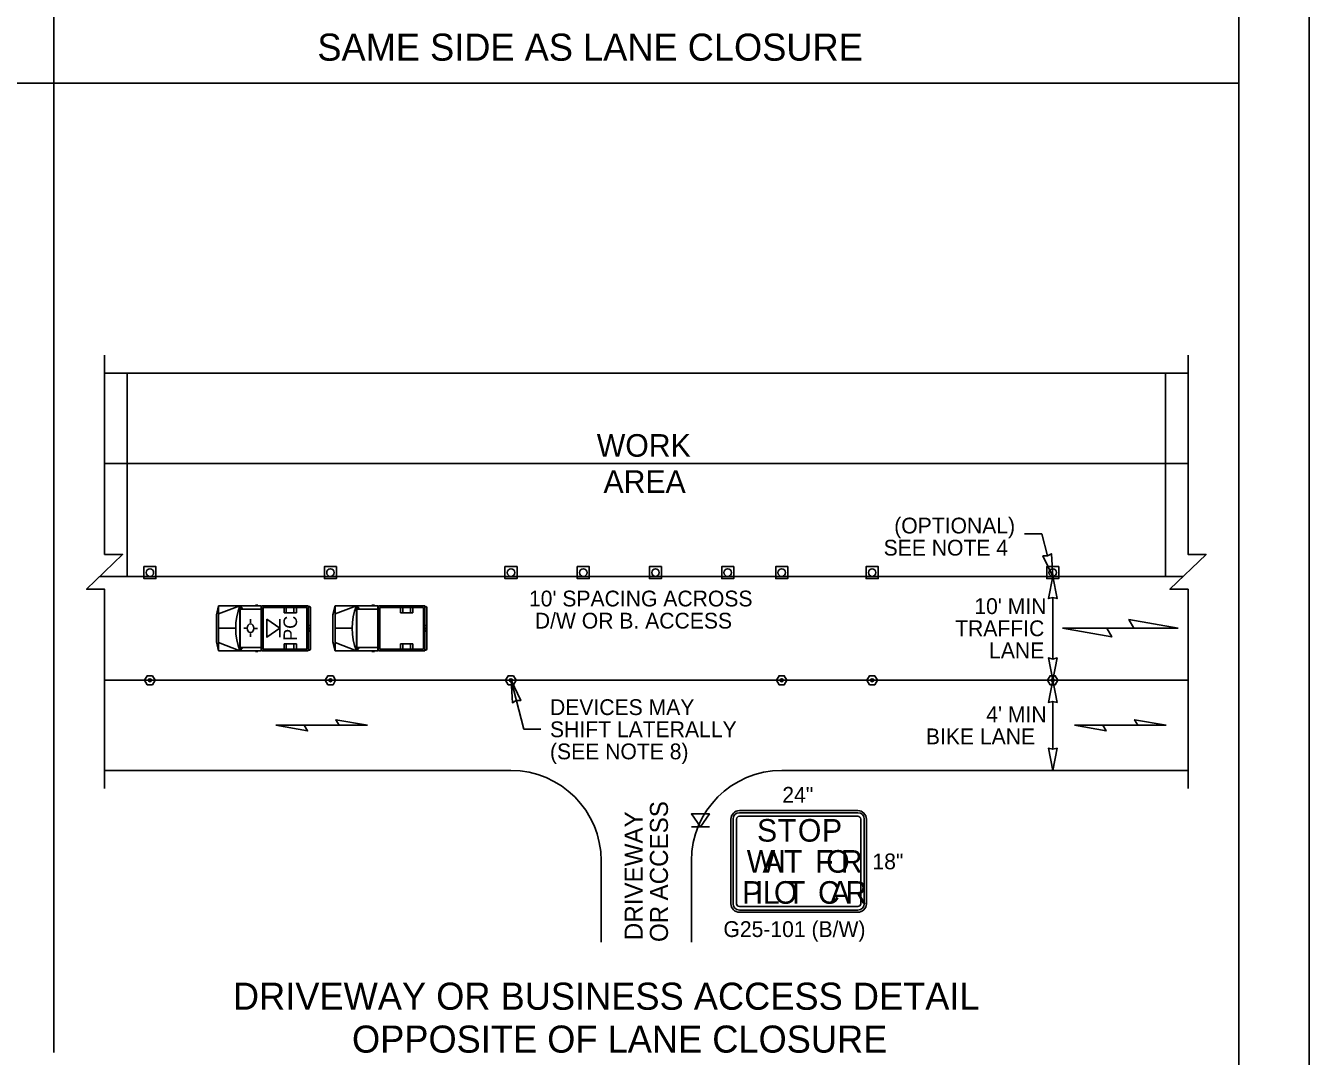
# Model space of a CAD drawing. Extents: x 99999.1 to 100095.7, y 99995 to 100010.7.
# Drawn here: x 100070.38 to 100076.06, y 100001.67 to 100006.24 of the extents above; entities that cross this region are included whole.
import ezdxf

# ---------------------------------------------------------------- set-up
doc = ezdxf.new("R2010")
doc.units = 0
for name, color, linetype in [('RD_ED_DrivewayEdge', 7, 'Continuous'), ('RD_ED_ShoulderPavedEdge', 7, 'Continuous'), ('RD_MK_LineEdgeWhite', 7, 'Continuous'), ('RD_MK_LineSkipCenter', 7, 'Continuous'), ('SH_DE_DetailHeading2Text', 7, 'Continuous'), ('SH_GI_PlotLimits', 7, 'Continuous'), ('SH_GI_SheetBorder', 7, 'Continuous'), ('TR_SN_ConstructionSigns', 7, 'Continuous'), ('TR_WZ_MotoristVehicle', 7, 'Continuous'), ('TR_WZ_PortableSignMountBlk-Wht', 7, 'Continuous'), ('TR_WZ_TrafficCone', 7, 'Continuous'), ('TR_WZ_TubularMarker', 7, 'Continuous'), ('TR_WZ_WorkAreaLabel', 7, 'Continuous'), ('TR_WZ_WorkZoneDetails', 7, 'Continuous'), ('TR_WZ_WorkZoneTextCurrent', 7, 'Continuous')]:
    doc.layers.add(name, color=color, linetype=linetype)

msp = doc.modelspace()

# ---------------------------------------------------------------- linework, layer by layer
at = {"layer": 'RD_ED_DrivewayEdge'}
for p, q in [((100072.925, 100002.5359), (100072.925, 100002.1759)), ((100073.325, 100002.5359), (100073.325, 100002.1759))]:
    msp.add_line(p, q, dxfattribs=at)
for centre, start, end in [((100072.525, 100002.5359), 0, 90), ((100073.725, 100002.5359), 90, 180)]:
    msp.add_arc(centre, 0.4, start, end, dxfattribs=at)
at = {"layer": 'RD_ED_ShoulderPavedEdge'}
for p, q in [((100070.725, 100004.6959), (100075.525, 100004.6959)), ((100070.725, 100002.9359), (100072.525, 100002.9359)), ((100073.725, 100002.9359), (100075.525, 100002.9359))]:
    msp.add_line(p, q, dxfattribs=at)
at = {"layer": 'RD_MK_LineEdgeWhite'}
for p, q in [((100070.725, 100004.2959), (100075.525, 100004.2959)), ((100070.725, 100003.3359), (100075.525, 100003.3359))]:
    msp.add_line(p, q, dxfattribs=at)
at = {"layer": 'RD_MK_LineSkipCenter'}
msp.add_lwpolyline([(100075.5043, 100003.7959), (100070.7043, 100003.7959)], dxfattribs=at)
at = {"layer": 'SH_GI_PlotLimits'}
msp.add_lwpolyline([(100059.0625, 99999.6875), (100076.0625, 99999.6875), (100076.0625, 100010.6875), (100059.0625, 100010.6875)], close=True, dxfattribs=at)
at = {"layer": 'SH_GI_SheetBorder'}
msp.add_line((100075.75, 100010.375), (100075.75, 100000), dxfattribs=at)
at = {"layer": 'TR_SN_ConstructionSigns'}
for p, q in [((100073.5, 100002.3456), (100073.5, 100002.7206)), ((100073.5, 100002.7206), (100073.5, 100002.3456)), ((100073.5094, 100002.7206), (100073.5094, 100002.3456)), ((100073.525, 100002.3456), (100073.525, 100002.7206)), ((100073.5375, 100002.7581), (100074.0625, 100002.7581)), ((100074.0625, 100002.7581), (100073.5375, 100002.7581)), ((100074.0625, 100002.7488), (100073.5375, 100002.7488)), ((100073.5375, 100002.7331), (100074.0625, 100002.7331)), ((100074.075, 100002.7206), (100074.075, 100002.3456)), ((100074.0906, 100002.3456), (100074.0906, 100002.7206)), ((100074.1, 100002.7206), (100074.1, 100002.3456)), ((100074.1, 100002.3456), (100074.1, 100002.7206)), ((100074.0625, 100002.3331), (100073.5375, 100002.3331)), ((100073.5375, 100002.3175), (100074.0625, 100002.3175)), ((100074.0625, 100002.3081), (100073.5375, 100002.3081)), ((100073.5375, 100002.3081), (100074.0625, 100002.3081))]:
    msp.add_line(p, q, dxfattribs=at)
for centre, radius, start, end in [((100073.5375, 100002.7206), 0.0375, 90, 180), ((100073.5375, 100002.7206), 0.0375, 90, 180), ((100073.5375, 100002.7206), 0.0281, 90, 180), ((100073.5375, 100002.7206), 0.0125, 90, 180), ((100074.0625, 100002.7206), 0.0375, 0, 90), ((100074.0625, 100002.7206), 0.0375, 0, 90), ((100074.0625, 100002.7206), 0.0281, 0, 90), ((100074.0625, 100002.7206), 0.0125, 0, 90), ((100073.5375, 100002.3456), 0.0375, 180, 270), ((100073.5375, 100002.3456), 0.0375, 180, 270), ((100073.5375, 100002.3456), 0.0281, 180, 270), ((100073.5375, 100002.3456), 0.0125, 180, 270), ((100074.0625, 100002.3456), 0.0375, 270, 0), ((100074.0625, 100002.3456), 0.0375, 270, 0), ((100074.0625, 100002.3456), 0.0281, 270, 0), ((100074.0625, 100002.3456), 0.0125, 270, 0)]:
    msp.add_arc(centre, radius, start, end, dxfattribs=at)
at = {"layer": 'TR_WZ_MotoristVehicle'}
for p, q in [((100071.23, 100003.6659), (100071.2207, 100003.6255)), ((100071.2207, 100003.6255), (100071.2207, 100003.5063)), ((100071.23, 100003.6659), (100071.23, 100003.4659)), ((100071.23, 100003.6659), (100071.4189, 100003.6659)), ((100071.23, 100003.6293), (100071.3245, 100003.6659)), ((100071.3245, 100003.6659), (100071.3245, 100003.4659)), ((100071.3262, 100003.6659), (100071.3262, 100003.4659)), ((100071.3262, 100003.6659), (100071.3382, 100003.6504)), ((100071.3262, 100003.6504), (100071.4189, 100003.6504)), ((100071.3932, 100003.6687), (100071.4045, 100003.6687)), ((100071.4189, 100003.6659), (100071.4189, 100003.4659)), ((100071.6274, 100003.6659), (100071.4217, 100003.6659)), ((100071.4217, 100003.6659), (100071.4217, 100003.4659)), ((100071.6215, 100003.6579), (100071.4275, 100003.6579)), ((100071.4275, 100003.6579), (100071.4275, 100003.4739)), ((100071.5202, 100003.6579), (100071.5202, 100003.6349)), ((100071.5752, 100003.6349), (100071.5202, 100003.6349)), ((100071.5302, 100003.6579), (100071.5302, 100003.6349)), ((100071.5642, 100003.6579), (100071.5642, 100003.6349)), ((100071.5752, 100003.6579), (100071.5752, 100003.6349)), ((100071.6215, 100003.6579), (100071.6215, 100003.4739)), ((100071.6274, 100003.6659), (100071.6274, 100003.4659)), ((100071.6325, 100003.6626), (100071.6281, 100003.6626)), ((100071.6281, 100003.6626), (100071.6281, 100003.4692)), ((100071.637, 100003.6565), (100071.637, 100003.4753)), ((100071.7463, 100003.6659), (100071.737, 100003.6255)), ((100071.737, 100003.6255), (100071.737, 100003.5063)), ((100071.7463, 100003.6659), (100071.7463, 100003.4659)), ((100071.7463, 100003.6659), (100071.9352, 100003.6659)), ((100071.7463, 100003.6293), (100071.8407, 100003.6659)), ((100071.8407, 100003.6659), (100071.8407, 100003.4659)), ((100071.8424, 100003.6659), (100071.8424, 100003.4659)), ((100071.8424, 100003.6659), (100071.8545, 100003.6504)), ((100071.8424, 100003.6504), (100071.9352, 100003.6504)), ((100071.9094, 100003.6687), (100071.9207, 100003.6687)), ((100071.9352, 100003.6659), (100071.9352, 100003.4659)), ((100072.1436, 100003.6659), (100071.9379, 100003.6659)), ((100071.9379, 100003.6659), (100071.9379, 100003.4659)), ((100072.1378, 100003.6579), (100071.9438, 100003.6579)), ((100071.9438, 100003.6579), (100071.9438, 100003.4739)), ((100072.0365, 100003.6579), (100072.0365, 100003.6349)), ((100072.0914, 100003.6349), (100072.0365, 100003.6349)), ((100072.0465, 100003.6579), (100072.0465, 100003.6349)), ((100072.0805, 100003.6579), (100072.0805, 100003.6349)), ((100072.0914, 100003.6579), (100072.0914, 100003.6349)), ((100072.1378, 100003.6579), (100072.1378, 100003.4739)), ((100072.1436, 100003.6659), (100072.1436, 100003.4659)), ((100072.1488, 100003.6626), (100072.1443, 100003.6626)), ((100072.1443, 100003.6626), (100072.1443, 100003.4692)), ((100072.1533, 100003.6565), (100072.1533, 100003.4753)), ((100071.3715, 100003.6055), (100071.3715, 100003.5894)), ((100071.637, 100003.58), (100071.6281, 100003.5762)), ((100071.6325, 100003.5687), (100071.6325, 100003.5631)), ((100072.1533, 100003.58), (100072.1443, 100003.5762)), ((100072.1488, 100003.5687), (100072.1488, 100003.5631)), ((100071.23, 100003.5659), (100071.3059, 100003.5659)), ((100071.3414, 100003.566), (100071.354, 100003.566)), ((100071.3722, 100003.5274), (100071.3719, 100003.5425)), ((100071.3856, 100003.5656), (100071.3856, 100003.5656)), ((100071.4024, 100003.5651), (100071.3875, 100003.5655)), ((100071.637, 100003.5518), (100071.6281, 100003.5556)), ((100071.6346, 100003.5659), (100071.6305, 100003.5659)), ((100071.7463, 100003.5659), (100071.8222, 100003.5659)), ((100072.1533, 100003.5518), (100072.1443, 100003.5556)), ((100072.1509, 100003.5659), (100072.1467, 100003.5659)), ((100071.23, 100003.4659), (100071.2207, 100003.5063)), ((100071.23, 100003.5025), (100071.3245, 100003.4659)), ((100071.23, 100003.4659), (100071.4189, 100003.4659)), ((100071.3262, 100003.4814), (100071.4189, 100003.4814)), ((100071.3361, 100003.4814), (100071.3262, 100003.4659)), ((100071.3932, 100003.4631), (100071.4045, 100003.4631)), ((100071.6274, 100003.4659), (100071.4217, 100003.4659)), ((100071.6215, 100003.4739), (100071.4275, 100003.4739)), ((100071.5202, 100003.4739), (100071.5202, 100003.4969)), ((100071.5752, 100003.4969), (100071.5202, 100003.4969)), ((100071.5302, 100003.4739), (100071.5302, 100003.4969)), ((100071.5642, 100003.4739), (100071.5642, 100003.4969)), ((100071.5752, 100003.4739), (100071.5752, 100003.4969)), ((100071.6325, 100003.4692), (100071.6281, 100003.4692)), ((100071.7463, 100003.4659), (100071.737, 100003.5063)), ((100071.7463, 100003.5025), (100071.8407, 100003.4659)), ((100071.7463, 100003.4659), (100071.9352, 100003.4659)), ((100071.8424, 100003.4814), (100071.9352, 100003.4814)), ((100071.8524, 100003.4814), (100071.8424, 100003.4659)), ((100071.9094, 100003.4631), (100071.9207, 100003.4631)), ((100072.1436, 100003.4659), (100071.9379, 100003.4659)), ((100072.1378, 100003.4739), (100071.9438, 100003.4739)), ((100072.0365, 100003.4739), (100072.0365, 100003.4969)), ((100072.0914, 100003.4969), (100072.0365, 100003.4969)), ((100072.0465, 100003.4739), (100072.0465, 100003.4969)), ((100072.0805, 100003.4739), (100072.0805, 100003.4969)), ((100072.0914, 100003.4739), (100072.0914, 100003.4969)), ((100072.1488, 100003.4692), (100072.1443, 100003.4692))]:
    msp.add_line(p, q, dxfattribs=at)
for centre, major_axis, start_param, end_param in [((100071.4595, 100003.5659), (0, -0.2099), 4.215667, 5.208926), ((100071.6325, 100003.6565), (0, 0.0061), 4.712389, 6.283185), ((100071.9757, 100003.5659), (0, -0.2099), 4.215667, 5.208926), ((100072.1488, 100003.6565), (0, 0.0061), 4.712389, 6.283185), ((100071.6325, 100003.4753), (0, -0.0061), 0, 1.570796), ((100072.1488, 100003.4753), (0, -0.0061), 0, 1.570796)]:
    msp.add_ellipse(centre, major_axis=major_axis, ratio=0.73155, start_param=start_param, end_param=end_param, dxfattribs=at)
for centre, major_axis in [((100071.3715, 100003.5659), (0, 0.0193)), ((100071.6325, 100003.5659), (0, 0.00282)), ((100072.1488, 100003.5659), (0, 0.00282))]:
    msp.add_ellipse(centre, major_axis=major_axis, ratio=0.73155, dxfattribs=at)
at = {"layer": 'TR_WZ_PortableSignMountBlk-Wht'}
for p, q in [((100071.5013, 100003.6058), (100071.5013, 100003.5258)), ((100073.405, 100002.6859), (100073.325, 100002.6859))]:
    msp.add_line(p, q, dxfattribs=at)
for points in [[(100071.5013, 100003.5659), (100071.4439, 100003.5258), (100071.4439, 100003.6058)], [(100073.3651, 100002.6859), (100073.325, 100002.7434), (100073.405, 100002.7434)]]:
    msp.add_lwpolyline(points, close=True, dxfattribs=at)
at = {"layer": 'TR_WZ_TrafficCone'}
for points in [[(100070.899, 100003.8392), (100070.9524, 100003.8392), (100070.9524, 100003.7859), (100070.899, 100003.7859), (100070.899, 100003.8392)], [(100070.899, 100003.7859), (100070.9524, 100003.7859), (100070.9524, 100003.8392), (100070.899, 100003.8392), (100070.899, 100003.7859)], [(100071.699, 100003.8392), (100071.7524, 100003.8392), (100071.7524, 100003.7859), (100071.699, 100003.7859), (100071.699, 100003.8392)], [(100071.699, 100003.7859), (100071.7524, 100003.7859), (100071.7524, 100003.8392), (100071.699, 100003.8392), (100071.699, 100003.7859)], [(100072.499, 100003.8392), (100072.5524, 100003.8392), (100072.5524, 100003.7859), (100072.499, 100003.7859), (100072.499, 100003.8392)], [(100072.499, 100003.7859), (100072.5524, 100003.7859), (100072.5524, 100003.8392), (100072.499, 100003.8392), (100072.499, 100003.7859)], [(100072.819, 100003.8392), (100072.8723, 100003.8392), (100072.8723, 100003.7859), (100072.819, 100003.7859), (100072.819, 100003.8392)], [(100072.819, 100003.7859), (100072.8723, 100003.7859), (100072.8723, 100003.8392), (100072.819, 100003.8392), (100072.819, 100003.7859)], [(100073.139, 100003.8392), (100073.1923, 100003.8392), (100073.1923, 100003.7859), (100073.139, 100003.7859), (100073.139, 100003.8392)], [(100073.139, 100003.7859), (100073.1923, 100003.7859), (100073.1923, 100003.8392), (100073.139, 100003.8392), (100073.139, 100003.7859)], [(100073.459, 100003.8392), (100073.5123, 100003.8392), (100073.5123, 100003.7859), (100073.459, 100003.7859), (100073.459, 100003.8392)], [(100073.459, 100003.7859), (100073.5123, 100003.7859), (100073.5123, 100003.8392), (100073.459, 100003.8392), (100073.459, 100003.7859)], [(100073.6983, 100003.8392), (100073.7517, 100003.8392), (100073.7517, 100003.7859), (100073.6983, 100003.7859), (100073.6983, 100003.8392)], [(100073.6983, 100003.7859), (100073.7517, 100003.7859), (100073.7517, 100003.8392), (100073.6983, 100003.8392), (100073.6983, 100003.7859)], [(100074.099, 100003.8392), (100074.1524, 100003.8392), (100074.1524, 100003.7859), (100074.099, 100003.7859), (100074.099, 100003.8392)], [(100074.099, 100003.7859), (100074.1524, 100003.7859), (100074.1524, 100003.8392), (100074.099, 100003.8392), (100074.099, 100003.7859)], [(100074.899, 100003.8392), (100074.9524, 100003.8392), (100074.9524, 100003.7859), (100074.899, 100003.7859), (100074.899, 100003.8392)], [(100074.899, 100003.7859), (100074.9524, 100003.7859), (100074.9524, 100003.8392), (100074.899, 100003.8392), (100074.899, 100003.7859)]]:
    msp.add_lwpolyline(points, dxfattribs=at)
for centre in [(100070.9257, 100003.8126), (100071.7257, 100003.8126), (100072.5257, 100003.8126), (100072.8457, 100003.8126), (100073.1657, 100003.8126), (100073.4857, 100003.8126), (100073.725, 100003.8126), (100074.1257, 100003.8126), (100074.9257, 100003.8126)]:
    msp.add_circle(centre, 0.0167, dxfattribs=at)
at = {"layer": 'TR_WZ_TubularMarker'}
for points in [[(100070.9026, 100003.3359), (100070.9142, 100003.3559), (100070.9373, 100003.3559), (100070.9488, 100003.3359), (100070.9373, 100003.3159), (100070.9142, 100003.3159)], [(100071.7026, 100003.3359), (100071.7142, 100003.3559), (100071.7373, 100003.3559), (100071.7488, 100003.3359), (100071.7373, 100003.3159), (100071.7142, 100003.3159)], [(100072.5019, 100003.3359), (100072.5135, 100003.3559), (100072.5365, 100003.3559), (100072.5481, 100003.3359), (100072.5365, 100003.3159), (100072.5135, 100003.3159)], [(100073.7019, 100003.3359), (100073.7135, 100003.3559), (100073.7365, 100003.3559), (100073.7481, 100003.3359), (100073.7365, 100003.3159), (100073.7135, 100003.3159)], [(100074.1026, 100003.3359), (100074.1141, 100003.3559), (100074.1372, 100003.3559), (100074.1488, 100003.3359), (100074.1372, 100003.3159), (100074.1141, 100003.3159)], [(100074.9026, 100003.3359), (100074.9141, 100003.3559), (100074.9372, 100003.3559), (100074.9488, 100003.3359), (100074.9372, 100003.3159), (100074.9141, 100003.3159)]]:
    msp.add_lwpolyline(points, close=True, dxfattribs=at)
for points in [[(100070.9142, 100003.3159), (100070.9373, 100003.3159), (100070.9488, 100003.3359), (100070.9373, 100003.3559), (100070.9142, 100003.3559), (100070.9026, 100003.3359), (100070.9142, 100003.3159)], [(100071.7142, 100003.3159), (100071.7373, 100003.3159), (100071.7488, 100003.3359), (100071.7373, 100003.3559), (100071.7142, 100003.3559), (100071.7026, 100003.3359), (100071.7142, 100003.3159)], [(100072.5135, 100003.3159), (100072.5365, 100003.3159), (100072.5481, 100003.3359), (100072.5365, 100003.3559), (100072.5135, 100003.3559), (100072.5019, 100003.3359), (100072.5135, 100003.3159)], [(100073.7135, 100003.3159), (100073.7365, 100003.3159), (100073.7481, 100003.3359), (100073.7365, 100003.3559), (100073.7135, 100003.3559), (100073.7019, 100003.3359), (100073.7135, 100003.3159)], [(100074.1141, 100003.3159), (100074.1372, 100003.3159), (100074.1488, 100003.3359), (100074.1372, 100003.3559), (100074.1141, 100003.3559), (100074.1026, 100003.3359), (100074.1141, 100003.3159)], [(100074.9141, 100003.3159), (100074.9372, 100003.3159), (100074.9488, 100003.3359), (100074.9372, 100003.3559), (100074.9141, 100003.3559), (100074.9026, 100003.3359), (100074.9141, 100003.3159)]]:
    msp.add_lwpolyline(points, dxfattribs=at)
for centre in [(100070.9257, 100003.3359), (100071.7257, 100003.3359), (100072.525, 100003.3359), (100073.725, 100003.3359), (100074.1257, 100003.3359), (100074.9257, 100003.3359)]:
    msp.add_circle(centre, 0.00667, dxfattribs=at)
at = {"layer": 'TR_WZ_WorkZoneDetails'}
for p, q in [((100070.5, 100010.275), (100070.5, 100001.6859)), ((100070.5, 100005.9804), (100065.25, 100005.9804)), ((100075.75, 100005.9804), (100070.5, 100005.9804)), ((100074.8007, 100003.9839), (100074.8769, 100003.9839)), ((100074.9022, 100003.8866), (100074.8769, 100003.9839)), ((100074.9256, 100003.4296), (100074.9256, 100003.7022)), ((100075.2856, 100003.5659), (100075.0445, 100003.5659)), ((100075.1651, 100003.5659), (100075.4062, 100003.5659)), ((100072.5257, 100003.3359), (100072.5821, 100003.1184)), ((100074.9256, 100003.0296), (100074.9256, 100003.2422)), ((100071.7642, 100003.1359), (100071.6098, 100003.1359)), ((100071.6098, 100003.1359), (100071.7642, 100003.1359)), ((100072.6583, 100003.1184), (100072.5821, 100003.1184)), ((100075.3025, 100003.1359), (100075.1482, 100003.1359)), ((100075.1482, 100003.1359), (100075.3025, 100003.1359)), ((100075.3025, 100003.1359), (100075.1482, 100003.1359)), ((100075.1482, 100003.1359), (100075.3025, 100003.1359)), ((100073.5, 100002.7206), (100073.5, 100002.3456)), ((100074.0625, 100002.7581), (100073.5375, 100002.7581)), ((100074.1, 100002.3456), (100074.1, 100002.7206)), ((100073.5375, 100002.3081), (100074.0625, 100002.3081))]:
    msp.add_line(p, q, dxfattribs=at)
for points in [[(100070.725, 100002.8559), (100070.725, 100003.7385), (100070.645, 100003.7385), (100070.805, 100003.8933), (100070.725, 100003.8933), (100070.725, 100004.7759)], [(100075.525, 100002.8559), (100075.525, 100003.7385), (100075.445, 100003.7385), (100075.605, 100003.8933), (100075.525, 100003.8933), (100075.525, 100004.7759)]]:
    msp.add_lwpolyline(points, dxfattribs=at)
for points in [[(100070.825, 100004.6959), (100070.825, 100003.7959), (100075.425, 100003.7959), (100075.425, 100004.6959)], [(100074.9257, 100003.7959), (100074.8824, 100003.8862), (100074.9022, 100003.8866), (100074.9197, 100003.8959)], [(100074.9257, 100003.7959), (100074.9064, 100003.6976), (100074.9257, 100003.7022), (100074.945, 100003.6976)], [(100075.4821, 100003.5659), (100075.2633, 100003.6045), (100075.2856, 100003.5659)], [(100074.9685, 100003.5659), (100075.1873, 100003.5273), (100075.1651, 100003.5659)], [(100074.9256, 100003.3359), (100074.9064, 100003.4342), (100074.9256, 100003.4296), (100074.9449, 100003.4342)], [(100072.5257, 100003.3359), (100072.569, 100003.2456), (100072.5492, 100003.2452), (100072.5316, 100003.2359)], [(100074.9256, 100003.3359), (100074.9064, 100003.2376), (100074.9256, 100003.2422), (100074.9449, 100003.2376)], [(100071.4841, 100003.1359), (100071.6241, 100003.1112), (100071.6098, 100003.1359)], [(100071.8899, 100003.1359), (100071.7499, 100003.1606), (100071.7642, 100003.1359)], [(100075.0224, 100003.1359), (100075.1624, 100003.1112), (100075.1482, 100003.1359)], [(100075.0224, 100003.1359), (100075.1624, 100003.1112), (100075.1482, 100003.1359)], [(100075.4283, 100003.1359), (100075.2882, 100003.1606), (100075.3025, 100003.1359)], [(100075.4283, 100003.1359), (100075.2882, 100003.1606), (100075.3025, 100003.1359)], [(100074.9256, 100002.9359), (100074.9064, 100003.0342), (100074.9256, 100003.0296), (100074.9449, 100003.0342)]]:
    msp.add_lwpolyline(points, close=True, dxfattribs=at)
for centre, start, end in [((100073.5375, 100002.7206), 90, 180), ((100074.0625, 100002.7206), 0, 90), ((100073.5375, 100002.3456), 180, 270), ((100074.0625, 100002.3456), 270, 0)]:
    msp.add_arc(centre, 0.0375, start, end, dxfattribs=at)

# ---------------------------------------------------------------- texts
at = {"layer": 'SH_DE_DetailHeading2Text'}
for s, p in [('SAME SIDE AS LANE CLOSURE', (100071.6677, 100006.0804)), ('DRIVEWAY OR BUSINESS ACCESS DETAIL', (100071.2936, 100001.8759)), ('OPPOSITE OF LANE CLOSURE', (100071.8211, 100001.6859))]:
    msp.add_text(s, height=0.12, rotation=360, dxfattribs=at).set_placement(p)
at = {"layer": 'TR_SN_ConstructionSigns'}
for s, p in [('24"', (100073.7276, 100002.7931)), ('18"', (100074.1269, 100002.4981)), ('G25-101 (B/W)', (100073.4667, 100002.1981))]:
    msp.add_text(s, height=0.07, rotation=360, dxfattribs=at).set_placement(p)
at = {"layer": 'TR_WZ_MotoristVehicle'}
msp.add_text('PC', height=0.06, rotation=90, dxfattribs=at).set_placement((100071.5777, 100003.5099))
at = {"layer": 'TR_WZ_WorkAreaLabel'}
for s, p in [('WORK', (100072.9058, 100004.3259)), ('AREA', (100072.9354, 100004.1659))]:
    msp.add_text(s, height=0.1, dxfattribs=at).set_placement(p)
at = {"layer": 'TR_WZ_WorkZoneDetails'}
for s, p in [('S', (100073.6155, 100002.6206)), ('T', (100073.7075, 100002.6206)), ('O', (100073.7965, 100002.6206)), ('P', (100073.9035, 100002.6206)), ('W', (100073.57, 100002.4831)), ('A', (100073.64, 100002.4831)), ('I', (100073.708, 100002.4831)), ('T', (100073.735, 100002.4831)), ('F', (100073.873, 100002.4831)), ('O', (100073.922, 100002.4831)), ('R', (100073.987, 100002.4831)), ('P', (100073.5495, 100002.3456)), ('I', (100073.6065, 100002.3456)), ('L', (100073.6415, 100002.3456)), ('O', (100073.6905, 100002.3456)), ('T', (100073.7475, 100002.3456)), ('C', (100073.8855, 100002.3456)), ('A', (100073.9395, 100002.3456)), ('R', (100074.0075, 100002.3456))]:
    msp.add_text(s, height=0.1, dxfattribs=at).set_placement(p)
at = {"layer": 'TR_WZ_WorkZoneTextCurrent'}
for s, p in [('(OPTIONAL)', (100074.2233, 100003.9859)), ('SEE NOTE 4', (100074.1764, 100003.8879)), ("10' SPACING ACROSS", (100072.605, 100003.6626)), ("10' MIN", (100074.5783, 100003.6289)), ('D/W OR B. ACCESS', (100072.6312, 100003.5646)), ('TRAFFIC', (100074.4933, 100003.5309)), ('LANE', (100074.6437, 100003.4329)), ('DEVICES MAY', (100072.6983, 100003.1814)), ("4' MIN", (100074.6312, 100003.1499)), ('SHIFT LATERALLY', (100072.6983, 100003.0834)), ('BIKE LANE', (100074.3637, 100003.0519)), ('(SEE NOTE 8)', (100072.6983, 100002.9854))]:
    msp.add_text(s, height=0.07, dxfattribs=at).set_placement(p)
for s, p in [('ACCESS', (100073.221, 100002.3602)), ('DRIVEWAY', (100073.109, 100002.1842)), ('OR', (100073.221, 100002.1759))]:
    msp.add_text(s, height=0.08, rotation=90, dxfattribs=at).set_placement(p)

doc.saveas('drawing.dxf')
